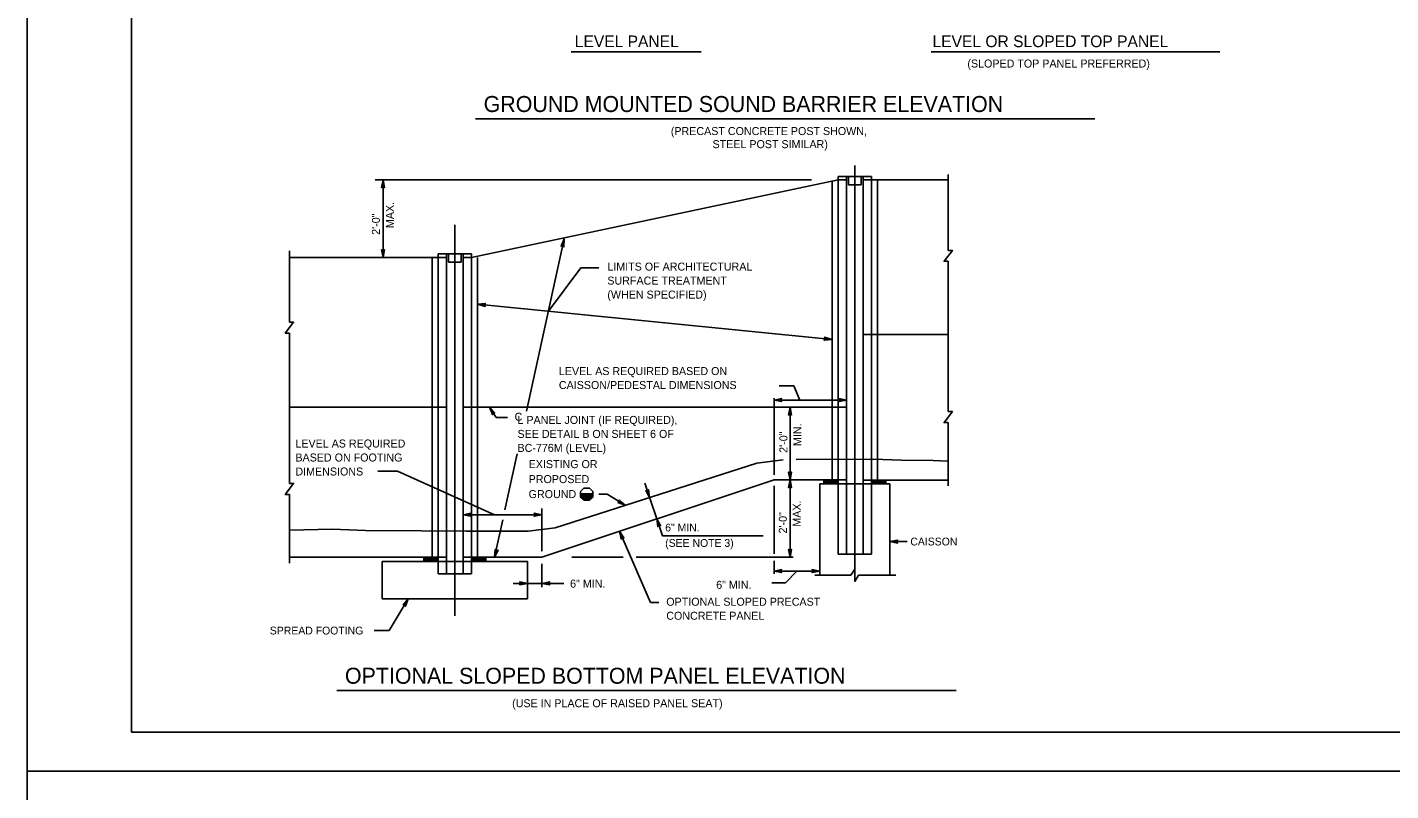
# Model space of a CAD drawing. Extents: x 3761 to 5458, y -616 to 1166.
# Drawn here: x 3761 to 4285, y -30 to 264 of the extents above; entities that cross this region are included whole.
import ezdxf

# ---------------------------------------------------------------- set-up
doc = ezdxf.new("R2010")
doc.units = 0
for name, color, linetype in [('1', 7, 'Continuous'), ('2', 7, 'Continuous'), ('PLT-BNDY', 7, 'Continuous')]:
    doc.layers.add(name, color=color, linetype=linetype)

msp = doc.modelspace()

# ---------------------------------------------------------------- linework, layer by layer
at = {"layer": '1'}
for p, q in [((3970.23, 254.07), (4020.1, 254.07)), ((4108.36, 254.07), (4219.26, 254.07)), ((3933.45, 228.34), (4171.27, 228.34)), ((4079.11, 55.41), (4079.11, 210.48)), ((4062.42, 204.88), (3894.93, 204.88)), ((3897.97, 175.13), (3897.97, 204.88)), ((3931.86, 175.13), (4072.76, 204.88)), ((4070.36, 89.68), (4070.36, 204.4)), ((4072.76, 88.09), (4072.76, 206.23)), ((4072.76, 206.23), (4085.45, 206.23)), ((4075.93, 204.88), (4072.76, 204.88)), ((4075.93, 61.11), (4075.93, 206.23)), ((4076.71, 203.03), (4076.71, 206.23)), ((4081.51, 203.03), (4081.51, 206.23)), ((4082.28, 61.11), (4082.28, 206.23)), ((4085.45, 204.88), (4082.28, 204.88)), ((4085.45, 204.88), (4114.98, 204.88)), ((4085.45, 88.09), (4085.45, 206.23)), ((4087.86, 89.51), (4087.86, 204.88)), ((4114.98, 177.8), (4114.98, 206.98)), ((4076.71, 203.03), (4081.51, 203.03)), ((3925.51, 37.35), (3925.51, 187.69)), ((3953.05, 116.07), (3967.5, 182.21)), ((3862.02, 150.2), (3862.02, 177.71)), ((3862.02, 175.13), (3919.16, 175.13)), ((3916.76, 59.93), (3916.76, 175.13)), ((3919.16, 58.34), (3919.16, 176.48)), ((3919.16, 176.48), (3931.86, 176.48)), ((3922.33, 175.13), (3919.16, 175.13)), ((3922.33, 53.54), (3922.33, 176.48)), ((3923.11, 173.28), (3923.11, 176.48)), ((3923.11, 173.28), (3927.91, 173.28)), ((3927.91, 173.28), (3927.91, 176.48)), ((3928.68, 53.54), (3928.68, 176.48)), ((3931.86, 175.13), (3928.68, 175.13)), ((3931.86, 58.34), (3931.86, 176.48)), ((3934.26, 59.93), (3934.26, 175.13)), ((4114.98, 115.85), (4114.98, 173.62)), ((3961.43, 154.44), (3973.91, 171.07)), ((3980.83, 171.07), (3973.91, 171.07)), ((4070.36, 143.6), (3934.26, 157.14)), ((3862.02, 88.26), (3862.02, 146.03)), ((4082.28, 145.54), (4114.98, 145.54)), ((4055.67, 125.75), (4050.06, 125.75)), ((4055.67, 125.75), (4058.04, 120.31)), ((4048.09, 91.55), (4048.09, 121.1)), ((3922.33, 117.53), (3862.02, 117.53)), ((4075.93, 117.53), (3928.68, 117.53)), ((3941.33, 113.57), (3938.79, 117.53)), ((4075.93, 120.31), (4048.09, 120.31)), ((4054.23, 59.93), (4054.23, 117.53)), ((3945.74, 113.57), (3941.33, 113.57)), ((4114.98, 87.38), (4114.98, 111.68)), ((3944.76, 78.14), (3949.46, 99.64)), ((3903.46, 92.94), (3895.98, 92.94)), ((3940.71, 76.24), (3903.46, 92.94)), ((4048.09, 89.68), (3958.97, 59.93)), ((4048.09, 89.68), (4072.67, 89.68)), ((4067.2, 88.09), (4067.2, 89.68)), ((4067.2, 89.49), (4072.2, 89.49)), ((4067.2, 89.29), (4072.2, 89.29)), ((4067.2, 89.09), (4072.2, 89.09)), ((4072.2, 88.09), (4072.2, 89.68)), ((4075.85, 89.68), (4072.67, 89.68)), ((4085.45, 89.51), (4082.28, 89.51)), ((4085.45, 89.51), (4114.98, 89.51)), ((4086.01, 88.09), (4086.01, 89.51)), ((4086.01, 89.29), (4091.01, 89.29)), ((4086.01, 89.09), (4091.01, 89.09)), ((4091.01, 88.09), (4091.01, 89.51)), ((3862.02, 57.67), (3862.02, 84.08)), ((3973.82, 84.22), (3978.44, 84.22)), ((3975.08, 86.41), (3973.83, 85.16)), ((3973.83, 85.16), (3973.83, 83.04)), ((3973.84, 84.12), (3978.44, 84.12)), ((3973.84, 84.02), (3978.44, 84.02)), ((3973.84, 83.92), (3978.44, 83.92)), ((3973.84, 83.82), (3978.44, 83.82)), ((3975.08, 86.41), (3977.2, 86.41)), ((3976.92, 84.22), (3978.44, 84.22)), ((3977.2, 86.41), (3978.45, 85.16)), ((3978.45, 85.16), (3978.45, 83.04)), ((3980.79, 84.09), (3984.05, 84.09)), ((3990.96, 79.86), (3984.05, 84.09)), ((4005.22, 68.18), (3998.48, 88.36)), ((4048.09, 61.22), (4048.09, 87.32)), ((4065.61, 53), (4065.61, 88.09)), ((4065.61, 88.09), (4092.6, 88.09)), ((4067.2, 88.89), (4072.2, 88.89)), ((4067.2, 88.69), (4072.2, 88.69)), ((4067.2, 88.49), (4072.2, 88.49)), ((4067.2, 88.29), (4072.2, 88.29)), ((4072.76, 61.11), (4072.76, 88.09)), ((4085.45, 61.11), (4085.45, 88.09)), ((4086.01, 88.89), (4091.01, 88.89)), ((4086.01, 88.69), (4091.01, 88.69)), ((4086.01, 88.49), (4091.01, 88.49)), ((4086.01, 88.29), (4091.01, 88.29)), ((4092.6, 53), (4092.6, 88.09)), ((3958.97, 62.29), (3958.97, 78.6)), ((3973.82, 83.32), (3978.44, 83.32)), ((3973.82, 83.22), (3978.44, 83.22)), ((3973.82, 83.12), (3978.44, 83.12)), ((3973.83, 83.72), (3978.44, 83.72)), ((3973.83, 83.62), (3978.44, 83.62)), ((3973.83, 83.52), (3978.44, 83.52)), ((3973.83, 83.42), (3978.44, 83.42)), ((3975.08, 81.79), (3973.83, 83.04)), ((3973.84, 83.02), (3978.39, 83.02)), ((3973.94, 82.92), (3978.3, 82.92)), ((3974.04, 82.82), (3978.2, 82.82)), ((3974.15, 82.72), (3978.11, 82.72)), ((3974.25, 82.62), (3978.01, 82.62)), ((3974.35, 82.52), (3977.91, 82.52)), ((3974.45, 82.42), (3977.82, 82.42)), ((3974.55, 82.32), (3977.72, 82.32)), ((3974.65, 82.22), (3977.63, 82.22)), ((3974.76, 82.12), (3977.53, 82.12)), ((3974.86, 82.02), (3977.43, 82.02)), ((3974.96, 81.92), (3977.34, 81.92)), ((3975.06, 81.82), (3977.24, 81.82)), ((3977.2, 81.79), (3978.45, 83.04)), ((3958.97, 76.24), (3928.68, 76.24)), ((3940.78, 59.93), (3943.93, 74.34)), ((3988.74, 69.87), (4000.6, 42.55)), ((4043.89, 68.18), (4005.22, 68.18)), ((4099.26, 65.94), (4092.6, 65.94)), ((3862.02, 59.93), (3919.16, 59.93)), ((3897.61, 58.34), (3953.4, 58.34)), ((3897.61, 43.94), (3897.61, 58.34)), ((3913.6, 58.34), (3913.6, 59.93)), ((3913.6, 59.74), (3918.59, 59.74)), ((3913.6, 59.54), (3918.59, 59.54)), ((3913.6, 59.34), (3918.59, 59.34)), ((3913.6, 59.14), (3918.59, 59.14)), ((3913.6, 58.94), (3918.59, 58.94)), ((3913.6, 58.74), (3918.59, 58.74)), ((3913.6, 58.54), (3918.59, 58.54)), ((3913.6, 58.34), (3918.59, 58.34)), ((3918.59, 58.34), (3918.59, 59.93)), ((3922.33, 59.93), (3919.16, 59.93)), ((3919.16, 53.54), (3919.16, 58.34)), ((3931.86, 59.93), (3928.68, 59.93)), ((3931.86, 59.93), (3958.97, 59.93)), ((3931.86, 53.54), (3931.86, 58.34)), ((3932.41, 58.34), (3932.41, 59.93)), ((3932.41, 59.74), (3937.41, 59.74)), ((3932.41, 59.54), (3937.41, 59.54)), ((3932.41, 59.34), (3937.41, 59.34)), ((3932.41, 59.14), (3937.41, 59.14)), ((3932.41, 58.94), (3937.41, 58.94)), ((3932.41, 58.74), (3937.41, 58.74)), ((3932.41, 58.54), (3937.41, 58.54)), ((3937.41, 58.34), (3937.41, 59.93)), ((3953.4, 43.94), (3953.4, 58.34)), ((3990.2, 59.93), (3970.46, 59.93)), ((4055.44, 59.93), (3995.14, 59.93)), ((4048.09, 53.54), (4048.09, 58.57)), ((4072.76, 61.11), (4085.45, 61.11)), ((3919.16, 53.54), (3931.86, 53.54)), ((3958.97, 48.42), (3958.97, 57.43)), ((4065.61, 54.61), (4048.09, 54.61)), ((4052.43, 50.04), (4056.78, 54.61)), ((4063.76, 53), (4077.55, 53)), ((4077.55, 53), (4079.07, 55.35)), ((4079.07, 55.35), (4079.05, 50.65)), ((4079.05, 50.65), (4080.57, 53)), ((4080.57, 53), (4094.79, 53)), ((3967.34, 49.88), (3947.91, 49.88)), ((4052.43, 50.04), (4047.29, 50.04)), ((3897.61, 43.94), (3953.4, 43.94)), ((3900.24, 31.79), (3907.63, 43.94)), ((4000.6, 42.55), (4003.86, 42.55)), ((3894.56, 31.79), (3900.24, 31.79)), ((3880.19, 8.65), (4118.01, 8.65))]:
    msp.add_line(p, q, dxfattribs=at)
for points in [[(3897.97, 204.88), (3898.53, 201.9), (3898.37, 202.13), (3898.17, 202.24), (3897.97, 202.28), (3897.77, 202.24), (3897.57, 202.13), (3897.41, 201.9), (3897.97, 204.88), (3897.57, 202.13), (3897.77, 202.24), (3897.97, 204.88), (3897.97, 202.28), (3898.17, 202.24), (3897.97, 204.88), (3898.37, 202.13)], [(3897.97, 175.13), (3897.41, 178.11), (3897.57, 177.88), (3897.77, 177.76), (3897.97, 177.73), (3898.17, 177.76), (3898.37, 177.88), (3898.53, 178.11), (3897.97, 175.13), (3898.37, 177.88), (3898.17, 177.76), (3897.97, 175.13), (3897.97, 177.73), (3897.77, 177.76), (3897.97, 175.13), (3897.57, 177.88)], [(3967.5, 182.21), (3967.41, 179.18), (3967.3, 179.44), (3967.13, 179.6), (3966.95, 179.67), (3966.74, 179.68), (3966.52, 179.61), (3966.32, 179.42), (3967.5, 182.21), (3966.52, 179.61), (3966.74, 179.68), (3967.5, 182.21), (3966.95, 179.67), (3967.13, 179.6), (3967.5, 182.21), (3967.3, 179.44)], [(4114.98, 173.62), (4113.39, 173.62), (4116.57, 177.8), (4114.98, 177.8)], [(3934.26, 157.14), (3937.28, 157.4), (3937.03, 157.27), (3936.9, 157.08), (3936.84, 156.89), (3936.86, 156.68), (3936.95, 156.47), (3937.17, 156.29), (3934.26, 157.14), (3936.95, 156.47), (3936.86, 156.68), (3934.26, 157.14), (3936.84, 156.89), (3936.9, 157.08), (3934.26, 157.14), (3937.03, 157.27)], [(3862.02, 146.03), (3860.43, 146.03), (3863.61, 150.2), (3862.02, 150.2)], [(4070.36, 143.6), (4067.33, 143.34), (4067.58, 143.47), (4067.72, 143.66), (4067.77, 143.85), (4067.76, 144.06), (4067.66, 144.27), (4067.44, 144.45), (4070.36, 143.6), (4067.66, 144.27), (4067.76, 144.06), (4070.36, 143.6), (4067.77, 143.85), (4067.72, 143.66), (4070.36, 143.6), (4067.58, 143.47)], [(4048.09, 120.31), (4051.07, 120.87), (4050.84, 120.71), (4050.73, 120.51), (4050.69, 120.31), (4050.73, 120.11), (4050.84, 119.91), (4051.07, 119.75), (4048.09, 120.31), (4050.84, 119.91), (4050.73, 120.11), (4048.09, 120.31), (4050.69, 120.31), (4050.73, 120.51), (4048.09, 120.31), (4050.84, 120.71)], [(4075.93, 120.31), (4072.95, 119.75), (4073.18, 119.91), (4073.3, 120.11), (4073.33, 120.31), (4073.3, 120.51), (4073.18, 120.71), (4072.95, 120.87), (4075.93, 120.31), (4073.18, 120.71), (4073.3, 120.51), (4075.93, 120.31), (4073.33, 120.31), (4073.3, 120.11), (4075.93, 120.31), (4073.18, 119.91)], [(3938.79, 117.53), (3940.87, 115.32), (3940.62, 115.42), (3940.38, 115.42), (3940.2, 115.34), (3940.05, 115.2), (3939.94, 114.99), (3939.93, 114.71), (3938.79, 117.53), (3939.94, 114.99), (3940.05, 115.2), (3938.79, 117.53), (3940.2, 115.34), (3940.38, 115.42), (3938.79, 117.53), (3940.62, 115.42)], [(4054.23, 117.53), (4054.79, 114.54), (4054.63, 114.77), (4054.43, 114.89), (4054.23, 114.93), (4054.03, 114.89), (4053.83, 114.77), (4053.67, 114.54), (4054.23, 117.53), (4053.83, 114.77), (4054.03, 114.89), (4054.23, 117.53), (4054.23, 114.93), (4054.43, 114.89), (4054.23, 117.53), (4054.63, 114.77)], [(4114.98, 111.68), (4113.39, 111.68), (4116.57, 115.85), (4114.98, 115.85)], [(3862.02, 70.27), (3878.39, 70.73), (3891.16, 70.15), (3912.69, 70.11), (3929.96, 69.98), (3953.72, 69.89), (3964.07, 71.26), (4041.54, 96.05), (4051.55, 97.4)], [(4056.56, 97.5), (4086.31, 97.66), (4096.84, 97.25), (4109.25, 97.11), (4114.79, 96.86)], [(4054.23, 89.68), (4053.67, 92.66), (4053.83, 92.43), (4054.03, 92.31), (4054.23, 92.28), (4054.43, 92.31), (4054.63, 92.43), (4054.79, 92.66), (4054.23, 89.68), (4054.63, 92.43), (4054.43, 92.31), (4054.23, 89.68), (4054.23, 92.28), (4054.03, 92.31), (4054.23, 89.68), (4053.83, 92.43)], [(4054.23, 89.68), (4054.79, 86.7), (4054.63, 86.93), (4054.43, 87.05), (4054.23, 87.08), (4054.03, 87.05), (4053.83, 86.93), (4053.67, 86.7), (4054.23, 89.68), (4053.83, 86.93), (4054.03, 87.05), (4054.23, 89.68), (4054.23, 87.08), (4054.43, 87.05), (4054.23, 89.68), (4054.63, 86.93)], [(3862.02, 84.08), (3860.43, 84.08), (3863.61, 88.26), (3862.02, 88.26)], [(4000.32, 82.86), (3998.85, 85.51), (3999.07, 85.34), (3999.3, 85.29), (3999.5, 85.32), (3999.68, 85.42), (3999.83, 85.6), (3999.91, 85.86), (4000.32, 82.86), (3999.83, 85.6), (3999.68, 85.42), (4000.32, 82.86), (3999.5, 85.32), (3999.3, 85.29), (4000.32, 82.86), (3999.07, 85.34)], [(3990.96, 79.86), (3988.13, 80.94), (3988.41, 80.96), (3988.61, 81.07), (3988.75, 81.22), (3988.82, 81.41), (3988.82, 81.64), (3988.71, 81.9), (3990.96, 79.86), (3988.82, 81.64), (3988.82, 81.41), (3990.96, 79.86), (3988.75, 81.22), (3988.61, 81.07), (3990.96, 79.86), (3988.41, 80.96)], [(3928.68, 76.24), (3931.66, 76.8), (3931.43, 76.64), (3931.31, 76.44), (3931.28, 76.24), (3931.31, 76.04), (3931.43, 75.84), (3931.66, 75.69), (3928.68, 76.24), (3931.43, 75.84), (3931.31, 76.04), (3928.68, 76.24), (3931.28, 76.24), (3931.31, 76.44), (3928.68, 76.24), (3931.43, 76.64)], [(3958.97, 76.24), (3955.98, 75.69), (3956.21, 75.84), (3956.33, 76.04), (3956.37, 76.24), (3956.33, 76.44), (3956.21, 76.64), (3955.98, 76.8), (3958.97, 76.24), (3956.21, 76.64), (3956.33, 76.44), (3958.97, 76.24), (3956.37, 76.24), (3956.33, 76.04), (3958.97, 76.24), (3956.21, 75.84)], [(4003.04, 74.72), (4004.51, 72.07), (4004.29, 72.24), (4004.06, 72.29), (4003.86, 72.26), (4003.68, 72.16), (4003.53, 71.99), (4003.45, 71.72), (4003.04, 74.72), (4003.53, 71.99), (4003.68, 72.16), (4003.04, 74.72), (4003.86, 72.26), (4004.06, 72.29), (4003.04, 74.72), (4004.29, 72.24)], [(3988.74, 69.87), (3990.45, 67.35), (3990.21, 67.5), (3989.98, 67.53), (3989.78, 67.48), (3989.61, 67.37), (3989.47, 67.18), (3989.42, 66.91), (3988.74, 69.87), (3989.47, 67.18), (3989.61, 67.37), (3988.74, 69.87), (3989.78, 67.48), (3989.98, 67.53), (3988.74, 69.87), (3990.21, 67.5)], [(3940.78, 59.93), (3941.04, 62.95), (3941.13, 62.69), (3941.29, 62.52), (3941.48, 62.43), (3941.68, 62.41), (3941.9, 62.47), (3942.12, 62.65), (3940.78, 59.93), (3941.9, 62.47), (3941.68, 62.41), (3940.78, 59.93), (3941.48, 62.43), (3941.29, 62.52), (3940.78, 59.93), (3941.13, 62.69)], [(4054.23, 59.93), (4053.67, 62.91), (4053.83, 62.68), (4054.03, 62.56), (4054.23, 62.53), (4054.43, 62.56), (4054.63, 62.68), (4054.79, 62.91), (4054.23, 59.93), (4054.63, 62.68), (4054.43, 62.56), (4054.23, 59.93), (4054.23, 62.53), (4054.03, 62.56), (4054.23, 59.93), (4053.83, 62.68)], [(4092.6, 65.94), (4095.58, 66.5), (4095.35, 66.34), (4095.23, 66.14), (4095.2, 65.94), (4095.23, 65.74), (4095.35, 65.54), (4095.58, 65.38), (4092.6, 65.94), (4095.35, 65.54), (4095.23, 65.74), (4092.6, 65.94), (4095.2, 65.94), (4095.23, 66.14), (4092.6, 65.94), (4095.35, 66.34)], [(4048.09, 54.61), (4051.07, 55.17), (4050.84, 55.01), (4050.73, 54.81), (4050.69, 54.61), (4050.73, 54.41), (4050.84, 54.21), (4051.07, 54.05), (4048.09, 54.61), (4050.84, 54.21), (4050.73, 54.41), (4048.09, 54.61), (4050.69, 54.61), (4050.73, 54.81), (4048.09, 54.61), (4050.84, 55.01)], [(4065.61, 54.61), (4062.63, 54.05), (4062.86, 54.21), (4062.98, 54.41), (4063.01, 54.61), (4062.98, 54.81), (4062.86, 55.01), (4062.63, 55.17), (4065.61, 54.61), (4062.86, 55.01), (4062.98, 54.81), (4065.61, 54.61), (4063.01, 54.61), (4062.98, 54.41), (4065.61, 54.61), (4062.86, 54.21)], [(4063.76, 53), (4077.55, 53), (4079.07, 55.35), (4079.05, 50.65), (4080.57, 53), (4094.79, 53)], [(4080.57, 53), (4079.05, 50.65), (4079.07, 55.35), (4077.55, 53)], [(3953.4, 49.88), (3950.42, 49.32), (3950.65, 49.48), (3950.76, 49.68), (3950.8, 49.88), (3950.76, 50.08), (3950.65, 50.28), (3950.42, 50.44), (3953.4, 49.88), (3950.65, 50.28), (3950.76, 50.08), (3953.4, 49.88), (3950.8, 49.88), (3950.76, 49.68), (3953.4, 49.88), (3950.65, 49.48)], [(3958.97, 49.88), (3961.95, 50.44), (3961.72, 50.28), (3961.6, 50.08), (3961.57, 49.88), (3961.6, 49.68), (3961.72, 49.48), (3961.95, 49.32), (3958.97, 49.88), (3961.72, 49.48), (3961.6, 49.68), (3958.97, 49.88), (3961.57, 49.88), (3961.6, 50.08), (3958.97, 49.88), (3961.72, 50.28)], [(3907.63, 43.94), (3906.56, 41.1), (3906.55, 41.24), (3906.54, 41.38), (3906.49, 41.48), (3906.44, 41.59), (3906.36, 41.65), (3906.28, 41.72), (3906.19, 41.76), (3906.09, 41.79), (3905.98, 41.79), (3905.86, 41.8), (3905.73, 41.74), (3905.61, 41.68), (3907.63, 43.94), (3905.73, 41.74), (3905.86, 41.8), (3907.63, 43.94), (3905.98, 41.79), (3906.09, 41.79), (3907.63, 43.94), (3906.19, 41.76), (3906.28, 41.72), (3907.63, 43.94), (3906.36, 41.65), (3906.44, 41.59), (3907.63, 43.94), (3906.49, 41.48), (3906.54, 41.38), (3907.63, 43.94), (3906.55, 41.24)]]:
    msp.add_lwpolyline(points, dxfattribs=at)
at = {"layer": '2'}
for p, q in [((3801.34, -7.31), (3801.34, 556.69)), ((4587.34, -7.31), (3801.34, -7.31))]:
    msp.add_line(p, q, dxfattribs=at)
at = {"layer": 'PLT-BNDY'}
for points in [[(3761.34, 571.69), (4602.34, 571.69), (4602.34, -22.31), (3761.34, -22.31)], [(3761.34, -22.31), (4602.34, -22.31), (4602.34, -616.31), (3761.34, -616.31)]]:
    msp.add_lwpolyline(points, close=True, dxfattribs=at)

# ---------------------------------------------------------------- texts
at = {"layer": '1'}
for s, height, p in [('LEVEL PANEL', 4.4774, (3971.57, 255.91)), ('LEVEL OR SLOPED TOP PANEL', 4.4774, (4108.94, 255.91)), ('(SLOPED TOP PANEL PREFERRED)', 3.072, (4122.33, 248.08)), ('GROUND MOUNTED SOUND BARRIER ELEVATION', 6.144, (3936.58, 230.99)), ('(PRECAST CONCRETE POST SHOWN,', 3.072, (4008.45, 222.13)), ('STEEL POST SIMILAR)', 3.072, (4024.47, 217.1)), ('LIMITS OF ARCHITECTURAL', 3.072, (3984.08, 170.05)), ('SURFACE TREATMENT', 3.072, (3984.08, 164.68)), ('(WHEN SPECIFIED)', 3.072, (3984.08, 159.3)), ('LEVEL AS REQUIRED BASED ON', 3.072, (3965.47, 129.91)), ('CAISSON/PEDESTAL DIMENSIONS', 3.072, (3965.47, 124.54)), ('C', 3.07, (3948.47, 112.35)), ('L PANEL JOINT (IF REQUIRED),', 3.072, (3949.58, 111.14)), ('LEVEL AS REQUIRED', 3.072, (3864.3, 102.07)), ('SEE DETAIL B ON SHEET 6 OF', 3.072, (3949.58, 105.77)), ('BASED ON FOOTING', 3.072, (3864.3, 96.7)), ('BC-776M (LEVEL)', 3.072, (3949.58, 100.39)), ('DIMENSIONS', 3.072, (3864.3, 91.32)), ('EXISTING OR ', 3.072, (3953.86, 94.16)), ('PROPOSED', 3.072, (3953.86, 88.4)), ('GROUND', 3.072, (3953.86, 82.64)), ('6" MIN.', 3, (4006.29, 69.82)), ('(SEE NOTE 3)', 3, (4006.29, 63.89)), ('CAISSON', 3, (4100.42, 64.45)), ('6" MIN.', 3.072, (3969.78, 48.23)), ('6" MIN.', 3.072, (4025.87, 47.78)), ('OPTIONAL SLOPED PRECAST', 3.072, (4006.71, 41.28)), ('CONCRETE PANEL', 3.072, (4006.71, 35.9)), ('SPREAD FOOTING', 3, (3854.48, 30.24)), ('OPTIONAL SLOPED BOTTOM PANEL ELEVATION', 6.144, (3883.32, 11.31)), ('(USE IN PLACE OF RAISED PANEL SEAT)', 3.072, (3947.52, 2.28))]:
    msp.add_text(s, height=height, dxfattribs=at).set_placement(p)
for s, p in [('MAX.', (3902.12, 186.39)), ('2\'-0"', (3896.75, 183.79)), ('MIN.', (4058.6, 102.64)), ('2\'-0"', (4053.22, 100.04)), ('MAX.', (4058.37, 71.66)), ('2\'-0"', (4053, 69.06))]:
    msp.add_text(s, height=3.072, rotation=90, dxfattribs=at).set_placement(p)

doc.saveas('drawing.dxf')
